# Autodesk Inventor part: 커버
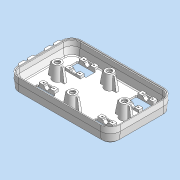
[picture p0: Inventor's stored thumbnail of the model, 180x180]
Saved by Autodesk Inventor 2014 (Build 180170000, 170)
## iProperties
Company: 한국ATC센터
Created: 2015-05
Part Number: 커버
Document SubType Name: 모델링
Designer: KYOUNG IL JANG
Vendor: CBT Solutions
Material: 일반
Appearance: 기본값
Author: KYOUNG IL JANG
Comments: 파생
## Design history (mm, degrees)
derived "커버.ipt"
node "솔리드1"
node "솔리드 본체"
node "곡면 본체"
feature "솔리드1::커버.ipt" dims "d0" = 10
tag "피쳐 태그1"
